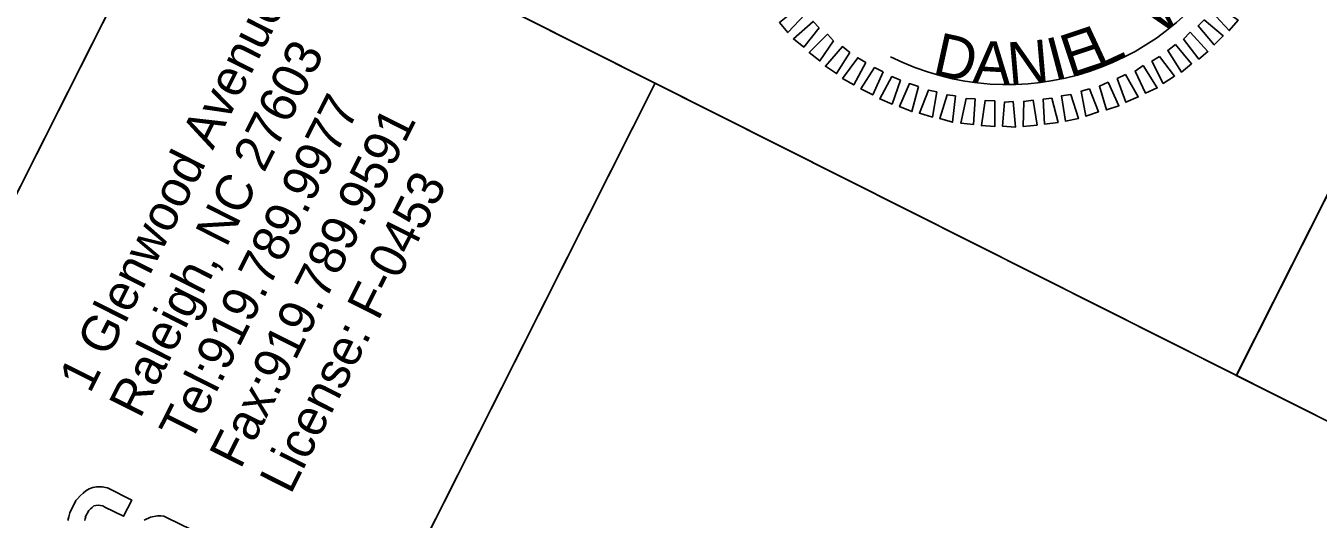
# Model space of a CAD drawing. Extents: x 2010322 to 2012069, y 441674 to 443687.
# Drawn here: x 2010986.8 to 2011152.3, y 443389 to 443452.2 of the extents above; entities that cross this region are included whole.
import ezdxf

# ---------------------------------------------------------------- set-up
doc = ezdxf.new("R2010")
doc.units = 0
for name, color, linetype in [('Old_Level_1', 7, 'Continuous'), ('Old_Level_2', 7, 'Continuous'), ('Old_Level_58', 7, 'Continuous'), ('Scratch_Level_0', 7, 'Continuous'), ('Sheet Clip Boundary CELL', 7, 'Continuous'), ('Sheet Plan And Profile CELL', 7, 'Continuous'), ('Sheet Professional Seal CELL', 7, 'Continuous'), ('Sheet Profile Grid Minor CELL', 7, 'Continuous'), ('Sheet Sticker Exception Certification CELL', 7, 'Continuous')]:
    doc.layers.add(name, color=color, linetype=linetype)

msp = doc.modelspace()

# ---------------------------------------------------------------- linework, layer by layer
at = {"layer": 'Old_Level_1'}
for points in [[(2010994.36, 443388.78), (2010994.38, 443389.06), (2010994.47, 443389.18), (2010994.41, 443389.22), (2010994.85, 443390.07), (2010995.08, 443390.27), (2010995.3, 443390.47), (2010995.52, 443390.67), (2010995.75, 443390.7), (2010996.09, 443390.74), (2010996.37, 443390.7), (2010996.66, 443390.65), (2010996.93, 443390.51), (2010999.32, 443389.33), (2011000.35, 443391.39), (2010997.25, 443392.95), (2010996.53, 443393.1), (2010995.88, 443393.11), (2010995.39, 443393.02), (2010994.91, 443392.85), (2010994.46, 443392.58), (2010994.12, 443392.28), (2010994.12, 443392.28), (2010993.74, 443391.96), (2010993.41, 443391.58), (2010993.19, 443391.33), (2010992.44, 443389.75), (2010992.28, 443389.24), (2010992.15, 443388.79)], [(2011007.97, 443387.62), (2011004.89, 443389.12), (2011004.46, 443389.32), (2011004.07, 443389.37), (2011003.67, 443389.36), (2011002.75, 443389.22), (2011001.93, 443388.84)]]:
    msp.add_lwpolyline(points, dxfattribs=at)
at = {"layer": 'Old_Level_58'}
msp.add_lwpolyline([(2010917.88, 443296.17), (2011007.84, 443474.86), (2011067.41, 443444.87), (2010977.45, 443266.18)], close=True, dxfattribs=at)
at = {"layer": 'Scratch_Level_0'}
msp.add_arc((2011112.57, 443478.04), 33.36, 243.277, 63.277, dxfattribs=at)
at = {"layer": 'Sheet Clip Boundary CELL'}
msp.add_lwpolyline([(2011359.68, 441843.44), (2012033.06, 443180.92), (2011922.92, 443238.13), (2011759.16, 443078.9), (2011595.22, 443247.25), (2011606.93, 443258.94), (2011612.2, 443362.21), (2011388.82, 443474.46), (2011348.46, 443524.76), (2011259.26, 443569.48), (2011170.42, 443393.01), (2011067.41, 443444.87), (2010977.45, 443266.18), (2010917.88, 443296.17), (2010676.94, 442817.58), (2010544.65, 442554.81), (2010423.28, 442313.75), (2010551.1, 442249.4)], close=True, dxfattribs=at)
at = {"layer": 'Sheet Plan And Profile CELL'}
for points in [[(2011097.8, 443653.54), (2010423.28, 442313.75), (2011361.14, 441841.59), (2012035.65, 443181.38)], [(2011041.38, 443457.97), (2011086.37, 443547.34), (2011186.86, 443496.75), (2011141.87, 443407.38)]]:
    msp.add_lwpolyline(points, close=True, dxfattribs=at)
at = {"layer": 'Sheet Professional Seal CELL'}
for points in [[(2011086.61, 443453.71), (2011084.41, 443451.35), (2011083.32, 443452.63), (2011085.92, 443454.68)], [(2011139.41, 443454.84), (2011142.08, 443452.93), (2011140.96, 443451.6), (2011138.71, 443454.02)], [(2011137.75, 443452.99), (2011140.18, 443450.93), (2011139.03, 443449.77), (2011136.96, 443452.21)], [(2011088.42, 443451.96), (2011086.44, 443449.49), (2011085.12, 443450.54), (2011087.66, 443452.79)], [(2011135.93, 443451.39), (2011138.23, 443448.94), (2011137.06, 443447.96), (2011135.1, 443450.52)], [(2011090.27, 443450.3), (2011088.52, 443447.72), (2011087.15, 443448.79), (2011089.51, 443451.13)], [(2011134.07, 443449.8), (2011136.14, 443447.36), (2011134.82, 443446.29), (2011133.08, 443449.07)], [(2011092.36, 443448.8), (2011090.66, 443446.08), (2011089.23, 443447.02), (2011091.41, 443449.56)], [(2011094.4, 443447.5), (2011092.85, 443444.64), (2011091.42, 443445.47), (2011093.37, 443448.13)], [(2011132.01, 443448.27), (2011133.95, 443445.78), (2011132.51, 443444.82), (2011131.05, 443447.69)], [(2011096.61, 443446.33), (2011095.28, 443443.36), (2011093.76, 443444.12), (2011095.53, 443446.87)], [(2011129.93, 443447.13), (2011131.73, 443444.26), (2011130.21, 443443.58), (2011128.9, 443446.42)], [(2011098.86, 443445.25), (2011097.76, 443442.17), (2011096.19, 443442.84), (2011097.75, 443445.7)], [(2011101.14, 443444.44), (2011100.3, 443441.22), (2011098.72, 443441.85), (2011099.98, 443444.8)], [(2011125.43, 443444.98), (2011126.83, 443441.97), (2011125.21, 443441.44), (2011124.33, 443444.46)], [(2011127.66, 443445.98), (2011129.29, 443443.09), (2011127.72, 443442.42), (2011126.61, 443445.44)], [(2011103.49, 443443.76), (2011102.92, 443440.52), (2011101.27, 443441.02), (2011102.41, 443443.97)], [(2011105.9, 443443.22), (2011105.49, 443439.84), (2011103.88, 443440.32), (2011104.8, 443443.38)], [(2011120.66, 443443.4), (2011121.63, 443440.33), (2011119.96, 443440), (2011119.45, 443443.23)], [(2011123.05, 443444.15), (2011124.19, 443441.18), (2011122.57, 443440.65), (2011122, 443443.84)], [(2011108.4, 443442.85), (2011108.19, 443439.54), (2011106.56, 443439.75), (2011107.24, 443442.88)], [(2011110.91, 443442.6), (2011110.92, 443439.29), (2011109.2, 443439.43), (2011109.7, 443442.65)], [(2011113.28, 443442.53), (2011113.58, 443439.24), (2011111.9, 443439.36), (2011112.16, 443442.42)], [(2011115.83, 443442.7), (2011116.33, 443439.48), (2011114.57, 443439.3), (2011114.62, 443442.52)], [(2011118.24, 443442.94), (2011119.02, 443439.81), (2011117.29, 443439.61), (2011117.12, 443442.83)]]:
    msp.add_lwpolyline(points, close=True, dxfattribs=at)
at = {"layer": 'Sheet Sticker Exception Certification CELL'}
for p, q in [((2011141.85, 443407.39), (2011231.81, 443586.07)), ((2011170.42, 443393.01), (2011141.85, 443407.39))]:
    msp.add_line(p, q, dxfattribs=at)

# ---------------------------------------------------------------- texts
at = {"layer": 'Old_Level_2'}
for s, p in [('1 Glenwood Avenue', (2010995.01, 443404.96)), ('Raleigh, NC 27603', (2011001.43, 443401.73)), ('Tel:919.789.9977 ', (2011007.86, 443398.49)), ('Fax:919.789.9591', (2011014.29, 443395.25)), ('License: F-0453', (2011020.71, 443392.02))]:
    msp.add_text(s, height=4.6576, rotation=63.277, dxfattribs=at).set_placement(p)
at = {"layer": 'Sheet Profile Grid Minor CELL'}
for s, rotation, p in [('W', 40.1662, (2011132.06, 443450.82)), ('E', 18.3278, (2011120.53, 443445.53)), ('L', 24.9108, (2011124.21, 443446.66)), ('D', 347.5452, (2011102.77, 443446.03)), ('A', 356.6899, (2011107.99, 443444.88)), ('N', 4.8757, (2011112.75, 443444.57)), ('I', 14.8074, (2011118.52, 443445.1))]:
    msp.add_text(s, height=5.5, rotation=rotation, dxfattribs=at).set_placement(p)

doc.saveas('drawing.dxf')
